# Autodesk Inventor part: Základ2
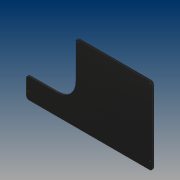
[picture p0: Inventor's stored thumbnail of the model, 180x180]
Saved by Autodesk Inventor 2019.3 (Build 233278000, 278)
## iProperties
Created: 2019-02
Part Number: Základ2
Material: Ocel, měkká, svařovaná
Document SubType Name: Modeling
Designer: B-hon
Density: 7.85 g/cm^3
Appearance: Černý – litý
Mass: 124070 g
Surface Area: 16665 cm^2
Volume: 15805 cm^3
Author: B-hon
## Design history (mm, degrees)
sketch "Náčrt1"
  geometry: L1 (0, 0)-(-1339, 0); L2 (-1339, 300)-(-1339, 800); L3 (-1339, 800)-(0, 800); L4 (0, 800)-(0, 0); L5 (-1339, 0)-(-1339, 0); L6 (-1339, 0)-(-1339, 300); L7 (-1339, 300)-(-1339, 300)
  constraints: 14 end point, 3 parallel, 2 horizontal, 2 perpendicular
  dimensions: "d0" = 1339 distance of L2.end L3.end; "d1" = 800 distance of L1.end L2.end; "d2" = 0 distance of L2.start L6.end; "d3" = 300 distance of L5.end L6.end
extrude "Vysunutí1" new body sketch "Náčrt1" distance "d4" = 15; taper "d5" = 0 deg
node "Upravit přímo2"
sketch "Náčrt2"
  geometry: L1 (-1494.146, 960.51)-(-814, 960.51); L2 (-814, 960.51)-(-814, 220); L3 (-814, 220)-(-1494.146, 220); L4 (-1494.146, 220)-(-1494.146, 960.51); L5 (-1339, 820)-(-1339, 0) reference; L6 (0, 820)-(-1339, 820) reference; 1 further point
  constraints: 8 end point, 2 parallel, 1 horizontal, 1 perpendicular
  dimensions: "d13" = 525 distance between parallel lines of L5 L2; "d14" = 600 distance between parallel lines of L3 L6
extrude "Vysunutí2" cut sketch "Náčrt2" distance "d15" = 30; taper "d16" = 0 deg
fillet "Zaoblení2" dims "d17" = 200
fillet "Zaoblení3" dims "d18" = 30
sketch "Náčrt3"
  geometry: L1 (-1339, 0)-(-30, 0) reference; L2 (-1014, 220)-(-1309, 220) reference; L3 (-1339, 190)-(-1339, 0) reference; L4 (-30, 820)-(-784, 820) reference; L5 (-814, 790)-(-814, 420) reference; L6 (0, 30)-(0, 790) reference; 8 further points
  dimensions: "d21" = 25 distance from line of point (-1314, 81.4) L3; "d23" = 25 distance from line of L5 point (-789, 795); "d25" = 25 distance from line of L4 point (-789, 795) (= d23); "d26" = 25 distance from line of L4 point (-25, 795) (= d23); "d27" = 25 distance from line of L6 point (-25, 795) (= d23); "d29" = 81.4 distance from line of L1 point (-25, 81.4); "d37" = 25 distance from line of L6 point (-25, 81.4); "d38" = 81.4 distance from line of L1 point (-1314, 81.4) (= d29)
hole "Díra1" sketch "Náčrt3" at (-789, 795), (-25, 795), (-25, 81.4), (-1314, 81.4) diameter "d30" = 10.5; stored, may be unused: countersink angle "d34" = 90 deg, drill point angle "d36" = 118 deg; dims "d31" = 6, "d32" = 4, "d33" = 2, "d35" = 8
fillet "Zaoblení4" dims "d39" = 30
node "Těleso1"
feature "Posunout2" dims "d11" = 20
other parameters: "d9" = 0, "d10" = 0
